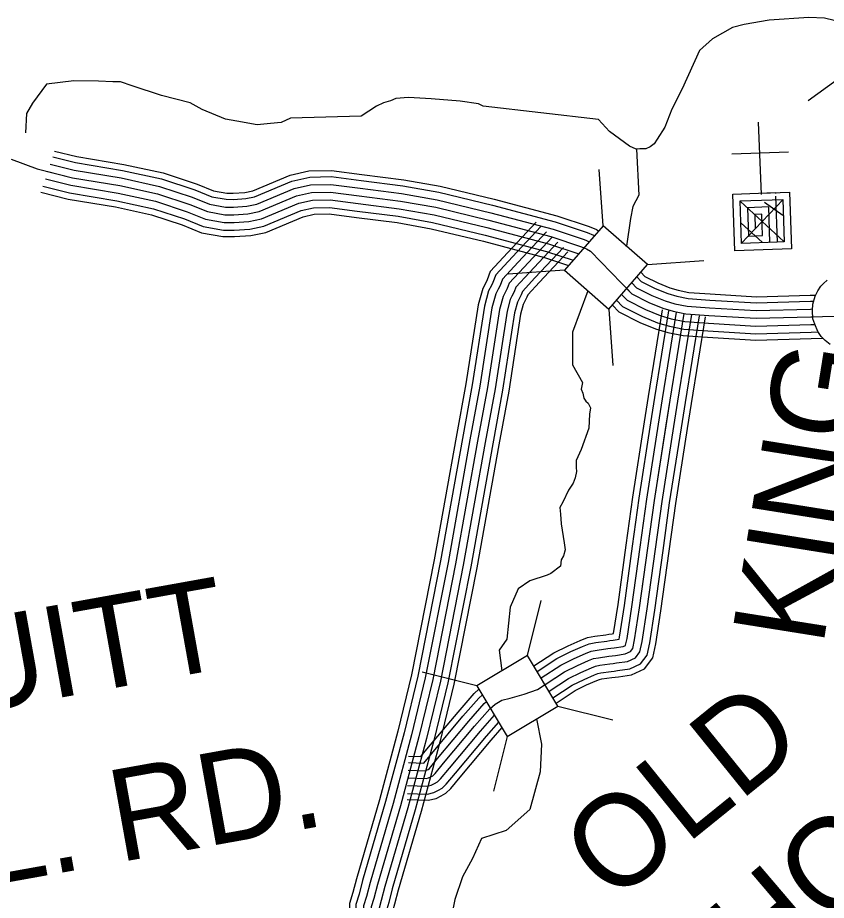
# Model space of a CAD drawing. Extents: x 1551132 to 1791609, y 378168 to 563823.
# Drawn here: x 1589716 to 1592970, y 433740 to 437290 of the extents above; entities that cross this region are included whole.
import ezdxf

# ---------------------------------------------------------------- set-up
doc = ezdxf.new("R2010")
doc.units = 0
for name, color, linetype in [('DESIGN - ROW - Right-of-Way and Easement Labels', 7, 'Continuous'), ('DESIGN - TRANSPORTATION - Text', 7, 'Continuous'), ('DESIGN - UTILITIES - Cable (Underground) with Text', 7, 'Continuous'), ('SURVEY - CONTOURS - Index with Text', 7, 'Continuous'), ('SURVEY - DRAINAGE - Storm Sewer', 7, 'Continuous'), ('SURVEY - TRANSPORTATION - Roads', 7, 'Continuous'), ('SURVEY - VEGETATION - Features with Text', 7, 'Continuous')]:
    doc.layers.add(name, color=color, linetype=linetype)

msp = doc.modelspace()

# ---------------------------------------------------------------- linework, layer by layer
at = {"layer": 'DESIGN - TRANSPORTATION - Text'}
for points in [[(1593098.308, 437200.53), (1593097.708, 437200.188), (1593001.668, 437279.207), (1592961.769, 437287.565), (1592899.829, 437290.124), (1592739.858, 437279.548), (1592639.785, 437262.44), (1592591.72, 437250.856), (1592511.397, 437205.546), (1592459.039, 437157.987), (1592389.241, 437003.466)], [(1590814.22, 436885.929), (1590776.104, 436868.261), (1590734.105, 436864.636), (1590680.089, 436859.119), (1590598.275, 436873.861), (1590552.376, 436882.278), (1590458.761, 436921.138), (1590411.021, 436947.588), (1590295.34, 436976.639), (1590177.751, 437015.723), (1590129.919, 437032.165), (1590099.945, 437032.432), (1590042.004, 437034.949), (1589942.082, 437035.849), (1589832.234, 437022.181), (1589776.077, 436946.563), (1589752.403, 436904.462), (1589748.728, 436826.326)], [(1592389.241, 437003.466), (1592348.417, 436921.522), (1592319.834, 436849.729), (1592289.46, 436801.969), (1592277.302, 436782.068), (1592261.211, 436770.201), (1592243.161, 436762.36), (1592219.178, 436762.576), (1592205.178, 436760.701), (1592177.296, 436772.951), (1592097.839, 436831.703), (1592053.132, 436880.046)], [(1592053.132, 436880.046), (1591589.776, 436933.63), (1591569.877, 436943.814), (1591496.012, 436954.489), (1591380.173, 436963.531), (1591288.275, 436968.356), (1591238.276, 436964.806), (1591216.21, 436954.997), (1591188.169, 436947.239), (1591160.07, 436933.48), (1591098.138, 436893.287), (1590814.22, 436885.929)], [(1592206.637, 436760.893), (1592215.061, 436575.78), (1592191.837, 436531.262), (1592182.162, 436481.902), (1592165.696, 436371.416), (1592161.313, 436372.666)], [(1592010.099, 436191.853), (1591948.451, 436024.957), (1591948.451, 435893.237), (1591988.233, 435823.326), (1591984, 435795.351), (1591989.866, 435779.284), (1591993.691, 435759.241), (1592001.583, 435747.158), (1592011.516, 435739.066), (1592021.357, 435720.965), (1592017.141, 435694.981), (1592014.674, 435638.972), (1591983.983, 435553.186), (1591963.625, 435509.343), (1591963.392, 435481.326), (1591965.258, 435465.3), (1591959.05, 435439.333), (1591950.867, 435417.399), (1591932.651, 435389.54), (1591910.268, 435341.714), (1591898.093, 435319.805), (1591899.876, 435293.771), (1591903.535, 435253.711), (1591914.893, 435177.559), (1591918.659, 435149.509), (1591912.459, 435125.55), (1591902.335, 435109.624), (1591900.118, 435083.632), (1591861.902, 435053.956), (1591846.794, 435048.056), (1591776.712, 435024.564), (1591729.364, 434992.988), (1591697.789, 434919.303), (1591684.639, 434790.366), (1591653.065, 434745.631), (1591664.873, 434663.663)], [(1591803.153, 434469.549), (1591824.061, 434368.013), (1591818.803, 434257.494), (1591776.712, 434104.873), (1591682.006, 434020.662), (1591581.958, 433989.12), (1591546.484, 433908.709), (1591505.893, 433835.024), (1591475.152, 433743.238), (1591464.711, 433689.295), (1591466.202, 433629.244), (1591461.694, 433567.242), (1591471.385, 433531.133), (1591485.052, 433492.982), (1591514.634, 433444.689), (1591532.317, 433408.505), (1591544.058, 433378.379), (1591545.892, 433358.345), (1591551.633, 433328.277), (1591554.7, 433303.102)]]:
    msp.add_lwpolyline(points, dxfattribs=at)
at = {"layer": 'DESIGN - UTILITIES - Cable (Underground) with Text'}
msp.add_line((1592817.94, 436749.485), (1592589.968, 436741.516), dxfattribs=at)
for points in [[(1592695.169, 436869.12), (1592707.806, 436578.938)], [(1592707.322, 436589.846), (1592707.539, 436584.788), (1592821.55, 436588.748), (1592829.469, 436360.825), (1592601.547, 436352.856), (1592593.578, 436580.778), (1592764.523, 436586.764), (1592764.699, 436582.722)], [(1592765.049, 436572.555), (1592771.517, 436387.309), (1592629.047, 436382.341), (1592623.054, 436553.278), (1592794.049, 436559.263), (1592799.985, 436388.326), (1592743.008, 436386.3), (1592738.032, 436528.77), (1592652.538, 436525.778), (1592656.548, 436411.817), (1592713.524, 436413.801), (1592710.531, 436499.294), (1592682.022, 436498.327), (1592684.048, 436441.301)], [(1592795.758, 436559.397), (1592626.931, 436381.324)], [(1592623.937, 436550.461), (1592798.801, 436390.301)], [(1592720.298, 436548.046), (1592795.1, 436495.153)], [(1592627.021, 436463.034), (1592711.366, 436387.225)]]:
    msp.add_lwpolyline(points, dxfattribs=at)
at = {"layer": 'SURVEY - CONTOURS - Index with Text'}
for points in [[(1589865.283, 436753.616), (1589954.881, 436731.416), (1590143.452, 436700.132), (1590301.815, 436665.506), (1590438.228, 436620.221), (1590504.227, 436593.946), (1590558.242, 436584.254), (1590583.741, 436584.062), (1590630.465, 436587.054), (1590662.398, 436593.754), (1590812.211, 436656.464), (1590888.309, 436673.656), (1590979.524, 436675.381), (1591101.721, 436659.664), (1591269.584, 436638.131), (1591416.072, 436612.197), (1591633.183, 436559.662), (1591886.144, 436492.777), (1592015.783, 436449.818), (1592044.824, 436437.443), (1592053.107, 436432.359)], [(1589689.896, 436720.39), (1589795.602, 436681.539), (1589937.332, 436646.422), (1590127.085, 436614.946), (1590278.832, 436581.762), (1590408.504, 436538.719), (1590480.294, 436510.135), (1590550.192, 436497.593), (1590586.183, 436497.318), (1590642.207, 436500.91), (1590688.272, 436510.577), (1590838.702, 436573.545), (1590898.792, 436587.121), (1590974.791, 436588.554), (1591090.671, 436573.654), (1591256.501, 436552.378), (1591398.297, 436527.278), (1591611.901, 436475.593), (1591861.403, 436409.625), (1591985.092, 436368.632), (1592004.916, 436360.182), (1592020.958, 436350.332), (1592062.648, 436307.956), (1592187.712, 436178.811), (1592255.452, 436144.252), (1592311.284, 436121.801), (1592353.191, 436109.468), (1592405.115, 436099.059), (1592497.055, 436092.359), (1592686.95, 436080.917), (1592906.97, 436087.276), (1593096.974, 436091.859)], [(1589847.675, 436700.573), (1589943.606, 436676.806), (1590132.935, 436645.397), (1590287.048, 436611.696), (1590419.129, 436567.853), (1590488.852, 436540.094), (1590553.067, 436528.569), (1590585.308, 436528.327), (1590638.007, 436531.702), (1590679.022, 436540.311), (1590829.227, 436603.188), (1590895.042, 436618.055), (1590976.482, 436619.588), (1591094.621, 436604.405), (1591261.176, 436583.029), (1591404.647, 436557.637), (1591619.509, 436505.644), (1591870.253, 436439.351), (1591996.067, 436397.658), (1592017.133, 436388.675)], [(1589857.525, 436730.074), (1589949.881, 436707.19), (1590138.785, 436675.856), (1590295.265, 436641.638), (1590429.753, 436596.996), (1590497.41, 436570.053), (1590555.942, 436559.553), (1590584.433, 436559.336), (1590633.815, 436562.503), (1590669.773, 436570.045), (1590819.761, 436632.83), (1590891.301, 436648.989), (1590978.174, 436650.631), (1591098.571, 436635.147), (1591265.85, 436613.688), (1591411.005, 436587.996), (1591627.117, 436535.703), (1591879.094, 436469.077), (1592007.033, 436426.676), (1592033.449, 436415.417), (1592036.757, 436413.384)], [(1589837.742, 436671.097), (1589937.332, 436646.422), (1590127.085, 436614.946), (1590278.832, 436581.762), (1590408.504, 436538.719), (1590480.294, 436510.135), (1590550.192, 436497.593), (1590586.183, 436497.318), (1590642.207, 436500.91), (1590688.272, 436510.577), (1590838.702, 436573.545), (1590898.792, 436587.121), (1590974.791, 436588.554), (1591090.671, 436573.654), (1591256.501, 436552.378), (1591398.297, 436527.278), (1591611.901, 436475.593), (1591861.403, 436409.625), (1591985.092, 436368.632), (1591994.767, 436364.507)], [(1589828.026, 436641.563), (1589931.057, 436616.038), (1590121.236, 436584.495), (1590270.615, 436551.828), (1590397.879, 436509.585), (1590471.736, 436480.176), (1590547.317, 436466.617), (1590587.058, 436466.309), (1590646.407, 436470.118), (1590697.522, 436480.843), (1590848.177, 436543.903), (1590902.542, 436556.187), (1590973.099, 436557.52), (1591086.721, 436542.903), (1591251.826, 436521.728), (1591391.947, 436496.919), (1591604.292, 436445.542), (1591852.553, 436379.899), (1591973.725, 436339.74)], [(1589818.126, 436612.079), (1589924.782, 436585.653), (1590115.386, 436554.036), (1590262.399, 436521.885), (1590387.254, 436480.443), (1590463.177, 436450.217), (1590544.442, 436435.633), (1590587.933, 436435.3), (1590650.598, 436439.317), (1590706.772, 436451.109), (1590857.643, 436514.26), (1590906.284, 436525.252), (1590971.407, 436526.478), (1591082.771, 436512.161), (1591247.151, 436491.068), (1591385.589, 436466.56), (1591596.684, 436415.483), (1591843.712, 436350.173), (1591951.093, 436314.589)], [(1589809.726, 436587.67), (1589919.582, 436560.453), (1590110.527, 436528.777), (1590255.582, 436497.051), (1590378.438, 436456.275), (1590456.078, 436425.358), (1590542.051, 436409.933), (1590588.658, 436409.574), (1590654.081, 436413.774), (1590714.447, 436426.441), (1590865.501, 436489.668), (1590909.392, 436499.585), (1590969.999, 436500.727), (1591079.496, 436486.652), (1591243.268, 436465.634), (1591380.323, 436441.376), (1591590.376, 436390.549), (1591836.37, 436325.506), (1591932.268, 436293.73)], [(1592207.461, 436247.538), (1592225.069, 436229.354), (1592281.151, 436200.745), (1592331.65, 436180.436), (1592368.066, 436169.719), (1592413.49, 436160.611), (1592501.171, 436154.227), (1592687.925, 436142.969), (1592905.328, 436149.252), (1592918.786, 436149.577)], [(1592223.719, 436266.288), (1592239.969, 436249.504), (1592291.401, 436223.262), (1592339.767, 436203.812), (1592373.991, 436193.745), (1592416.832, 436185.153), (1592502.813, 436178.886), (1592688.308, 436167.711), (1592904.67, 436173.961), (1592926.878, 436174.495)], [(1592166.679, 436200.536), (1592187.712, 436178.811), (1592255.452, 436144.252), (1592311.284, 436121.801), (1592353.191, 436109.468), (1592405.115, 436099.059), (1592497.055, 436092.359), (1592686.95, 436080.917), (1592906.97, 436087.276), (1592915.536, 436087.484)], [(1592187.104, 436223.995), (1592206.395, 436204.078), (1592268.302, 436172.494), (1592321.467, 436151.119), (1592360.624, 436139.593), (1592409.307, 436129.835), (1592499.113, 436123.293), (1592687.433, 436111.943), (1592906.145, 436118.268), (1592914.578, 436118.468)], [(1592146.33, 436176.977), (1592169.029, 436153.544), (1592242.602, 436116.009), (1592301.101, 436092.484), (1592345.758, 436079.342), (1592400.923, 436068.283), (1592494.996, 436061.425), (1592686.467, 436049.891), (1592907.795, 436056.283), (1592922.903, 436056.65)], [(1592108.972, 436134.026), (1592134.855, 436107.301), (1592219.086, 436064.333), (1592282.476, 436038.841), (1592332.15, 436024.224), (1592393.265, 436011.973), (1592491.23, 436004.832), (1592685.575, 435993.123), (1592909.295, 435999.59), (1592955.635, 436000.707)], [(1592126.013, 436153.402), (1592150.354, 436128.268), (1592229.752, 436087.759), (1592290.918, 436063.166), (1592338.317, 436049.216), (1592396.74, 436037.507), (1592492.938, 436030.491), (1592685.975, 436018.865), (1592908.612, 436025.299), (1592936.869, 436025.982)]]:
    msp.add_lwpolyline(points, dxfattribs=at)
at = {"layer": 'SURVEY - DRAINAGE - Storm Sewer'}
for p, q in [((1593080.224, 437089.751), (1592896.477, 436956.238)), ((1592071.577, 436453.239), (1592055.721, 436679.814)), ((1592250.881, 436297.359), (1592477.456, 436313.215)), ((1591915.706, 436273.901), (1591689.123, 436258.07)), ((1592094.977, 436118.047), (1592110.841, 435891.505)), ((1591767.443, 434725.294), (1591822.396, 434945.663)), ((1591563.779, 434602.906), (1591343.402, 434657.85)), ((1591889.773, 434521.597), (1592110.175, 434466.652)), ((1591686.159, 434399.234), (1591631.223, 434178.865))]:
    msp.add_line(p, q, dxfattribs=at)
for points in [[(1591915.706, 436273.901), (1592095.019, 436118.039), (1592250.881, 436297.359), (1592071.577, 436453.239)], [(1591686.159, 434399.234), (1591889.814, 434521.639), (1591767.443, 434725.294), (1591563.779, 434602.906)]]:
    msp.add_lwpolyline(points, close=True, dxfattribs=at)
at = {"layer": 'SURVEY - TRANSPORTATION - Roads'}
for points in [[(1591802.846, 436467.86), (1591688.007, 436345.473), (1591617.584, 436268.988), (1591605.167, 436235.654), (1591599.317, 436224.212), (1591587.184, 436200.394), (1591569.018, 436135.026), (1591519.836, 435817.409), (1591480.245, 435602.612), (1591392.28, 435109.607), (1591300.998, 434646.804), (1591245.808, 434419.989), (1591172.059, 434144.39), (1591079.37, 433826.657), (1591065.028, 433771.189), (1591051.612, 433726.904), (1591051.12, 433668.253), (1591050.387, 433580.092), (1591139.168, 433254.484), (1591177.317, 433125.989), (1591210.708, 433038.128), (1591250.815, 432949.126), (1591295.122, 432888.157)], [(1591821.604, 436450.259), (1591706.848, 436327.964), (1591639.916, 436255.279), (1591628.742, 436225.287), (1591622.225, 436212.528), (1591611.267, 436191.019), (1591594.201, 436129.601), (1591545.193, 435813.109), (1591505.544, 435598.02), (1591417.563, 435104.857), (1591326.114, 434641.27), (1591270.724, 434413.622), (1591196.825, 434137.465), (1591104.169, 433819.832), (1591089.794, 433764.239), (1591077.295, 433722.988), (1591076.836, 433668.036), (1591076.136, 433583.426), (1591163.901, 433261.525), (1591201.7, 433134.23), (1591234.474, 433047.987), (1591273.173, 432962.109), (1591315.922, 432903.275)], [(1591844.203, 436429.051), (1591729.548, 436306.856), (1591666.841, 436238.754), (1591657.166, 436212.786), (1591649.841, 436198.436), (1591640.3, 436179.711), (1591624.55, 436123.051), (1591575.759, 435807.926), (1591536.052, 435592.487), (1591448.029, 435099.14), (1591356.397, 434634.603), (1591300.757, 434405.956), (1591226.683, 434129.115), (1591134.06, 433811.615), (1591119.652, 433755.855), (1591108.261, 433718.262), (1591107.836, 433667.778), (1591107.169, 433587.451), (1591193.717, 433270.017), (1591231.082, 433144.164), (1591263.115, 433059.879), (1591300.131, 432977.751), (1591341.005, 432921.492)], [(1591866.811, 436407.833), (1591752.255, 436285.747), (1591693.765, 436222.228), (1591685.59, 436200.286), (1591677.457, 436184.352), (1591669.332, 436168.41), (1591654.908, 436116.509), (1591606.325, 435802.742), (1591566.551, 435586.953), (1591478.494, 435093.415), (1591386.68, 434627.936), (1591330.797, 434398.28), (1591256.541, 434120.765), (1591163.951, 433803.39), (1591149.501, 433747.48), (1591139.218, 433713.546), (1591138.835, 433667.519), (1591138.201, 433591.476), (1591223.533, 433278.509), (1591260.473, 433154.098), (1591291.764, 433071.762), (1591327.08, 432993.394), (1591366.079, 432939.717)], [(1591866.811, 436407.833), (1591752.255, 436285.747), (1591693.765, 436222.228), (1591685.59, 436200.286), (1591677.457, 436184.352), (1591669.332, 436168.41), (1591654.908, 436116.509), (1591606.325, 435802.742), (1591566.551, 435586.953), (1591478.494, 435093.415), (1591386.68, 434627.936), (1591330.797, 434398.28), (1591256.541, 434120.765), (1591163.951, 433803.39), (1591149.501, 433747.48), (1591139.218, 433713.546), (1591138.835, 433667.519), (1591138.201, 433591.476), (1591223.533, 433278.509), (1591260.473, 433154.098), (1591291.764, 433071.762), (1591327.08, 432993.394), (1591366.079, 432939.717)], [(1591889.419, 436386.616), (1591774.963, 436264.638), (1591720.69, 436205.703), (1591714.015, 436187.786), (1591705.073, 436170.269), (1591698.365, 436157.11), (1591685.265, 436109.967), (1591636.891, 435797.559), (1591597.05, 435581.42), (1591508.96, 435087.69), (1591416.962, 434621.27), (1591360.838, 434390.605), (1591286.398, 434112.415), (1591193.842, 433795.164), (1591179.351, 433739.105), (1591170.176, 433708.829), (1591169.834, 433667.261), (1591169.234, 433595.501), (1591253.349, 433287.001), (1591289.864, 433164.031), (1591320.414, 433083.646), (1591354.029, 433009.036), (1591391.153, 432957.943)], [(1591912.018, 436365.407), (1591797.663, 436243.529), (1591747.614, 436189.178), (1591742.439, 436175.286), (1591732.689, 436156.177), (1591727.398, 436145.801), (1591715.615, 436103.417), (1591667.457, 435792.375), (1591627.558, 435575.886), (1591539.426, 435081.973), (1591447.245, 434614.603), (1591390.871, 434382.938), (1591316.256, 434104.064), (1591223.733, 433786.948), (1591209.208, 433730.721), (1591201.142, 433704.104), (1591200.833, 433667.003), (1591200.267, 433599.526), (1591283.165, 433295.493), (1591319.247, 433173.965), (1591349.055, 433095.538), (1591380.987, 433024.678), (1591416.236, 432976.16)], [(1591930.043, 436348.49), (1591815.771, 436226.704), (1591769.08, 436176.002), (1591765.097, 436165.319), (1591754.705, 436144.951), (1591750.547, 436136.793), (1591739.822, 436098.2), (1591691.832, 435788.242), (1591651.874, 435571.478), (1591563.726, 435077.407), (1591471.386, 434609.286), (1591414.82, 434376.822), (1591340.055, 434097.406), (1591247.574, 433780.389), (1591233.008, 433724.046), (1591225.824, 433700.345), (1591225.549, 433666.794), (1591225.016, 433602.734), (1591306.939, 433302.26), (1591342.68, 433181.882), (1591371.896, 433105.013), (1591402.47, 433037.153), (1591436.227, 432990.694)], [(1591286.407, 434232.393), (1591359.38, 434229.918), (1591369.721, 434232.268), (1591379.155, 434237.11), (1591386.646, 434241.46), (1591395.513, 434249.602), (1591429.837, 434291.328), (1591554.992, 434440.298), (1591615.533, 434509.8), (1591637.682, 434529.617), (1591663.798, 434545.393), (1591698.397, 434553.068), (1591753.929, 434568.602), (1591808.053, 434588.127), (1591916.567, 434659.204), (1591968.741, 434684.755), (1592012.882, 434704.372), (1592032.931, 434712.197), (1592052.947, 434716.022), (1592094.963, 434721.648), (1592120.979, 434725.414), (1592160.995, 434731.056), (1592182.178, 434740.79), (1592191.161, 434752.807), (1592198.586, 434787.183), (1592218.502, 434916.67), (1592278.068, 435348.414), (1592341.391, 435752.116), (1592397.69, 436100.551)], [(1592238.819, 435664.247), (1592254.768, 435765.908), (1592311.101, 436114.543)], [(1592264.226, 435660.264), (1592280.168, 435761.867), (1592336.483, 436110.443)], [(1592294.851, 435655.464), (1592310.775, 435756.992), (1592367.091, 436105.492)], [(1592325.475, 435650.655), (1592341.391, 435752.116), (1592397.69, 436100.551)], [(1592356.099, 435645.847), (1592372.007, 435747.241), (1592428.29, 436095.609)], [(1592386.724, 435641.047), (1592402.615, 435742.366), (1592458.897, 436090.659)], [(1592411.14, 435637.214), (1592427.031, 435738.483), (1592483.297, 436086.717)], [(1592164.653, 435168.168), (1592191.286, 435361.206), (1592238.819, 435664.264)], [(1592190.128, 435164.651), (1592216.727, 435357.456), (1592264.226, 435660.281)], [(1592220.835, 435160.409), (1592247.402, 435352.939), (1592294.851, 435655.472)], [(1592251.543, 435156.176), (1592278.068, 435348.414), (1592325.475, 435650.672)], [(1592282.251, 435151.942), (1592308.733, 435343.889), (1592356.099, 435645.872)], [(1592312.958, 435147.701), (1592339.408, 435339.372), (1592386.724, 435641.064)], [(1592337.441, 435144.326), (1592363.857, 435335.764), (1592411.14, 435637.239)], [(1592095.23, 434810.317), (1592108.571, 434812.25), (1592113.813, 434812.992), (1592131.704, 434929.336), (1592164.662, 435168.184)], [(1592098.913, 434784.866), (1592112.204, 434786.791), (1592135.787, 434790.116), (1592137.587, 434798.45), (1592157.153, 434925.62), (1592190.136, 435164.668)], [(1592103.363, 434754.19), (1592116.596, 434756.107), (1592152.178, 434761.124), (1592162.07, 434765.666), (1592162.287, 434765.957), (1592168.086, 434792.816), (1592187.828, 434921.145), (1592220.844, 435160.426)], [(1592107.804, 434723.506), (1592120.979, 434725.414), (1592160.995, 434731.056), (1592182.178, 434740.79), (1592191.161, 434752.807), (1592198.586, 434787.183), (1592218.502, 434916.67), (1592251.551, 435156.192)], [(1592112.246, 434692.822), (1592125.362, 434694.722), (1592169.811, 434700.989), (1592202.286, 434715.914), (1592220.035, 434739.657), (1592229.085, 434781.549), (1592249.176, 434912.194), (1592282.259, 435151.959)], [(1592116.696, 434662.146), (1592129.754, 434664.038), (1592178.636, 434670.93), (1592222.393, 434691.039), (1592248.91, 434726.506), (1592259.584, 434775.916), (1592279.851, 434907.719), (1592312.967, 435147.717)], [(1592120.237, 434637.679), (1592133.245, 434639.571), (1592185.669, 434646.962), (1592238.426, 434671.196), (1592271.934, 434716.023), (1592283.892, 434771.424), (1592304.308, 434904.153), (1592337.449, 435144.342)], [(1591792.695, 434682.93), (1591873.085, 434735.581), (1591931.625, 434764.249), (1591979.108, 434785.349), (1592008.549, 434796.841), (1592038.881, 434802.641), (1592082.872, 434808.533), (1592095.271, 434810.325)], [(1591806.095, 434660.963), (1591885.826, 434713.189), (1591942.508, 434740.948), (1591989.007, 434761.615), (1592015.698, 434772.024), (1592043.006, 434777.249), (1592086.413, 434783.058), (1592098.955, 434784.866)], [(1591822.036, 434634.345), (1591901.201, 434686.197), (1591955.625, 434712.847), (1592000.949, 434732.99), (1592024.315, 434742.115), (1592047.981, 434746.632), (1592090.688, 434752.357), (1592103.388, 434754.19)], [(1591838.161, 434607.845), (1591916.567, 434659.204), (1591968.741, 434684.755), (1592012.882, 434704.372), (1592032.931, 434712.197), (1592052.947, 434716.022), (1592094.963, 434721.648), (1592107.821, 434723.506)], [(1591854.202, 434581.302), (1591931.934, 434632.212), (1591981.857, 434656.663), (1592024.815, 434675.755), (1592041.548, 434682.28), (1592057.914, 434685.413), (1592099.238, 434690.939), (1592112.254, 434692.822)], [(1591869.96, 434554.56), (1591947.308, 434605.22), (1591994.974, 434628.562), (1592036.756, 434647.129), (1592050.164, 434652.371), (1592062.889, 434654.796), (1592103.513, 434660.238), (1592116.688, 434662.146)], [(1591882.818, 434533.434), (1591959.558, 434583.702), (1592005.432, 434606.161), (1592046.273, 434624.312), (1592057.031, 434628.512), (1592066.847, 434630.395), (1592106.921, 434635.754), (1592120.221, 434637.679)], [(1591288.507, 434294.361), (1591350.305, 434292.261), (1591350.389, 434292.336), (1591382.163, 434330.962), (1591507.877, 434480.608), (1591571.317, 434553.435), (1591586.167, 434566.727)], [(1591289.382, 434320.062), (1591338.522, 434318.395), (1591362.388, 434347.404), (1591488.336, 434497.325), (1591552.976, 434571.535), (1591572.217, 434588.744)], [(1591287.457, 434263.377), (1591356.422, 434261.035), (1591359.038, 434261.635), (1591364.288, 434264.319), (1591368.163, 434266.577), (1591372.946, 434270.969), (1591405.996, 434311.145), (1591531.434, 434460.449), (1591593.425, 434531.617), (1591602.266, 434539.526)], [(1591286.407, 434232.393), (1591359.38, 434229.918), (1591369.721, 434232.268), (1591379.155, 434237.11), (1591386.646, 434241.46), (1591395.513, 434249.602), (1591429.837, 434291.328), (1591554.992, 434440.298), (1591615.533, 434509.8), (1591618.324, 434512.3)], [(1591285.357, 434201.409), (1591362.338, 434198.8), (1591380.405, 434202.9), (1591394.021, 434209.9), (1591405.129, 434216.342), (1591418.079, 434228.234), (1591453.678, 434271.51), (1591578.55, 434420.148), (1591635.04, 434484.999)], [(1591283.465, 434145.724), (1591367.655, 434142.865), (1591399.596, 434150.124), (1591420.754, 434160.983), (1591438.345, 434171.199), (1591458.628, 434189.825), (1591496.518, 434235.885), (1591620.882, 434383.922), (1591665.406, 434435.04)], [(1591284.307, 434170.424), (1591365.297, 434167.683), (1591391.079, 434173.541), (1591408.896, 434182.683), (1591423.612, 434191.225), (1591440.636, 434206.867), (1591477.511, 434251.693), (1591602.108, 434399.989), (1591651.84, 434457.09)]]:
    msp.add_lwpolyline(points, dxfattribs=at)
at = {"layer": 'SURVEY - VEGETATION - Features with Text'}
msp.add_lwpolyline([(1592985.36, 435976.231), (1592965.102, 435991.548), (1592949.236, 436007.157), (1592935.719, 436027.291), (1592923.32, 436057.275), (1592915.97, 436078.509), (1592914.411, 436111.785), (1592915.078, 436138.219), (1592924.453, 436169.678), (1592935.178, 436191.537), (1592948.011, 436209.821), (1592958.727, 436220.846), (1592972.527, 436234.138)], dxfattribs=at)

# ---------------------------------------------------------------- texts
at = {"layer": 'DESIGN - ROW - Right-of-Way and Easement Labels'}
for s, height, rotation, p in [('KING', 370.0093, 80.914444, (1592955.901, 434757.716)), ('PRUITT', 369.992, 10.183581, (1588823.315, 434363.686)), ('OLD', 369.9988, 38.959186, (1592106.721, 433720.288)), ('HOL. RD.', 369.992, 10.183581, (1588851.222, 433663.935)), ('HOL.', 369.9993, 40.455319, (1592700.99, 433393.072))]:
    msp.add_text(s, height=height, rotation=rotation, dxfattribs=at).set_placement(p)

doc.saveas('drawing.dxf')
